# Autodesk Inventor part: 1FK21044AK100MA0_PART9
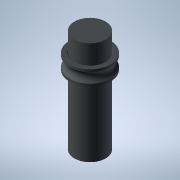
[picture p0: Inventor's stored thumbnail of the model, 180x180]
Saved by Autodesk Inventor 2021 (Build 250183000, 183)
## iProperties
Created: 2025-04
Part Number: 1FK21044AK100MA0_PART9
Material: Generic
Catalog Web Link: www.3dfindit.com
Description: -Servo synchronous motor
Document SubType Name: Modeling
Designer: psAdmin
Mass: 18.6788 g
Surface Area: 52.316 cm^2
Volume: 18.6788 cm^3
Density: 1 g/cm^3
Appearance: PSOLRGB-212-217-219
Category: PARTsolutions
Title: 1FK21044AK100MA0_PART9
Author: Cadenas PARTsolutions
Comments: Servo synchronous motor
Sending System: PARTsolutions
Preprocessor: ST-DEVELOPER v19.3
PSOL_IDENT_0: {$CADENAS_DATA/23d-libs/siemens_ag/_cat_/5e/d8/1fk21044ak100ma0.prj},213 {VTYP=3D},{NB=1FK21044AK100
PSOL_IDENT_1: MA0_PART9},{LINA=1FK21044AK100MA0_PART9},{NN=1FK21044AK100MA0_PART9},{NOPRJ=TRUE},{DATE=19.08.2025 1
PSOL_IDENT_2: 4:00:41},{GEOMDATE=30.07.2025 02:00:53},{VERSION=},{LINEID=10},{WBVAR=},{WBNUMERIC=}  {NB=1FK21044AK
PSOL_IDENT_3: 100MA0_PART9},{LINA=1FK21044AK100MA0_PART9},{KT=DUMMY},{PREVIEW=../../../_pool_/cb/72/p_d211_xx_0043
PSOL_IDENT_4: 4j.png},{DESCSHORT=SIMOTICS S-1FK2 HD, SINAMICS S210 3AC 400V-480V, 0.95 Nm, 6000 rpm},{DESCLONG=SIM
PSOL_IDENT_5: OTICS S-1FK2 HD servo motor M0=1.27 Nm; PN = 0.6 kW at nN=6000 rpm (380-480 V); PN = 0.4 kW at nN=30
PSOL_IDENT_6: 00 rpm (200-240 V); with holding brake; degree of protection IP64; cylindrical shaft D19x40mm; absol
PSOL_IDENT_7: ute encoder 22-bit + 12-bit multiturn (encoder AM22DQC); with OCC interface; plug size M17, rotatabl
PSOL_IDENT_8: e; SIMOTICS S-1FK2 servomotorfor a wide range of uses in industrial environments. SIMOTICS S‑1FK2 se
PSOL_IDENT_9: rvomotors are compact synchronous motors with a high dynamic performance that set themselves apart a
PSOL_IDENT_10: s a result of their high power density, degree of protection and overload capability. The motors are
PSOL_IDENT_11: available in two variants: as High Dynamic variant (highest dynamic performance as a result of the
PSOL_IDENT_12: low intrinsic moment of inertia for applications demanding a high dynamic performance with low moved
PSOL_IDENT_13: masses) - and as Compact variant (precise and stable closed-loop control for medium up to large mov
PSOL_IDENT_14: ed masses as a result of a medium intrinsic moment of inertia). SIMOTICSS‑1FK2 servomotors fully exp
PSOL_IDENT_15: loit their strengths in a system with the SINAMICSS210 frequency converter and simple connection usi
PSOL_IDENT_16: ng the one cable connection (OCC). Advantages include the short control and positioning times, fast
PSOL_IDENT_17: and precise correction of disturbing quantities as well as stable control with a high dynamic perfor
PSOL_IDENT_18: mance. The servo motors can be configured to address a wide range of requirements. For example with
PSOL_IDENT_19: and without holding brake, IP64 or IP65 degree of protection, singleturn or multiturn absolute encod
PSOL_IDENT_20: ers - to name just a few. Further, the servomotors are available in different shaft heights extendin
PSOL_IDENT_21: g from 20 to 100. A shaft sealing ring is available to achieve an IP65 degree of protection and for
PSOL_IDENT_22: subsequent mounting at the motor or as spare part. SIMOTICS - the optimum motor for each and every m
PSOL_IDENT_23: otion control application.},{INTNO=804766910005},{SUPPLIERALTNO=1FK2104-4AK10-0MA0},{MANUID=1FK21044
PSOL_IDENT_24: AK100MA0},{MANUNAME=Siemens},{MANUTYPEDESC=Synchronous motor 1FK2-HD 1,27 Nm},{AAU732=SIMOTICS},{AAO
PSOL_IDENT_25: 057=S-1FK2},{AAU734=SIMOTICS S-1FK2 HD servo motor M0=1.27 Nm; PN = 0.6 kW at nN=6000 rpm (380-480 V
PSOL_IDENT_26: ); PN = 0.4 kW at nN=3000 rpm (200-240 V); with holding brake; degree of protection IP64; cylindrica
PSOL_IDENT_27: l shaft D19x40mm; absolute encoder 22-bit + 12-bit multiturn (encoder AM22DQC); with OCC interface;
PSOL_IDENT_28: plug size M17, rotatable;},{AAW338=Synchronous motor 1FK2-HD 1,27 Nm},{AAO742=SIMOTICS},{AAO663=4042
PSOL_IDENT_29: 948691076},{NOCUPEROU=1},{PRICEQUANTITY=1},{QUANTITYMIN=1},{QUANTITYINT=1},{CTN=85015100},{COO=DE},{
PSOL_IDENT_30: AAO676=1FK2104-4AK10-0MA0},{AAO677=Siemens AG},{ORDERUNIT=C62},{CONTENTUNIT=C62}
NB: 1FK21044AK100MA0_PART9
NT: Servo synchronous motor
NBSYN: $MANUID._PART9
LINA: 1FK21044AK100MA0_PART9
CATALOG: SIEMENS
PREVIEW: ../../../_pool_/cb/72/p_d211_xx_00434j.png
DESCSHORT: SIMOTICS S-1FK2 HD, SINAMICS S210 3AC 400V-480V, 0.95 Nm, 6000 rpm
DESCLONG: SIMOTICS S-1FK2 HD servo motor M0=1.27 Nm; PN = 0.6 kW at nN=6000 rpm (380-480 V); PN = 0.4 kW at nN=3000 rpm (200-240 V); with holding brake; degree of protect
INTNO: 804766910005
SUPPLIERALTNO: 1FK2104-4AK10-0MA0
MANUID: 1FK21044AK100MA0
MANUNAME: Siemens
MANUTYPEDESC: Synchronous motor 1FK2-HD 1,27 Nm
AAU732: SIMOTICS
AAO057: S-1FK2
AAU734: SIMOTICS S-1FK2 HD servo motor M0=1.27 Nm; PN = 0.6 kW at nN=6000 rpm (380-480 V); PN = 0.4 kW at nN=3000 rpm (200-240 V); with holding brake; degree of protect
AAW338: Synchronous motor 1FK2-HD 1,27 Nm
AAO742: SIMOTICS
AAO663: 4042948691076.0
NOCUPEROU: 1
PRICEQUANTITY: 1
QUANTITYMIN: 1
QUANTITYINT: 1
CTN: 85015100
COO: DE
ARTICLENO: 1FK21044AK100MA0_PART9
BOMINFO: 1FK21044AK100MA0_PART9
CREATOR: CADENAS GmbH
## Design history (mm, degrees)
feature "2025_04_17_15_35_41_0968"
body "Solid1"
